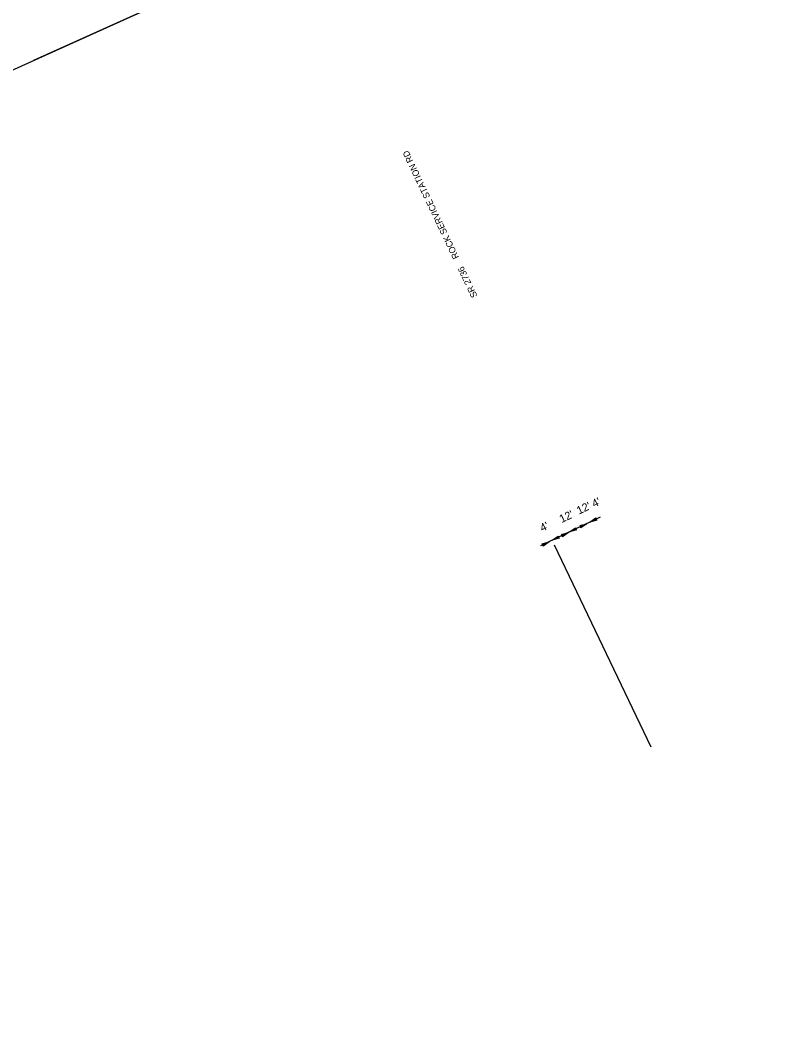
# Model space of a CAD drawing. Extents: x 2097307 to 2099001, y 683921 to 685907.
# Drawn here: x 2097686 to 2098154, y 684914 to 685550 of the extents above; entities that cross this region are included whole.
import ezdxf

# ---------------------------------------------------------------- set-up
doc = ezdxf.new("R2010")
doc.units = 0
for name, color, linetype in [('Default', 7, 'Continuous'), ('Matchline', 7, 'Continuous'), ('Prop Mkg Solid White Edge Line', 7, 'Continuous'), ('Sheet Layout Plan Border', 7, 'Continuous'), ('Text', 7, 'Continuous')]:
    doc.layers.add(name, color=color, linetype=linetype)

msp = doc.modelspace()

# ---------------------------------------------------------------- linework, layer by layer
at = {"layer": 'Default'}
msp.add_line((2098048.4, 685240), (2098011.01, 685222.07), dxfattribs=at)
for points in [[(2098035.72, 685234.78), (2098040.11, 685236.02), (2098036.38, 685233.35), (2098036.55, 685234.32)], [(2098046.38, 685238.17), (2098041.99, 685236.92), (2098045.72, 685239.6), (2098045.55, 685238.63)], [(2098022.8, 685226.87), (2098018.41, 685225.62), (2098022.14, 685228.3), (2098021.97, 685227.33)], [(2098024.19, 685229.25), (2098028.58, 685230.5), (2098024.85, 685227.82), (2098025.02, 685228.79)], [(2098033.69, 685232.08), (2098029.29, 685230.84), (2098033.03, 685233.51), (2098032.85, 685232.54)], [(2098012.14, 685223.48), (2098016.54, 685224.72), (2098012.8, 685222.04), (2098012.97, 685223.01)]]:
    msp.add_lwpolyline(points, close=True, dxfattribs=at)
at = {"layer": 'Matchline'}
msp.add_line((2097694.69, 685525.59), (2098013.7, 685669.59), dxfattribs=at)
at = {"layer": 'Prop Mkg Solid White Edge Line'}
msp.add_line((2098080.26, 685096.3), (2098019.77, 685222.59), dxfattribs=at)
at = {"layer": 'Sheet Layout Plan Border'}
msp.add_lwpolyline([(2098458.66, 685511.51), (2098911.14, 684517.12), (2097955.44, 684082.23), (2097420.98, 685256.77), (2097639.51, 685356.21), (2097584.97, 685476.06), (2098243.4, 685773.28), (2098379.01, 685475.27)], close=True, dxfattribs=at)

# ---------------------------------------------------------------- texts
at = {"layer": 'Text'}
for s, height, rotation, p in [('SR 2736    ROCK SERVICE STATION RD   ', 4, 115.42342, (2097971.8, 685378.34)), ("12'", 5, 25.61333, (2098035.13, 685241.63)), ("4'", 5, 25.61333, (2098044.64, 685245.94)), ("12'", 5, 25.61333, (2098024.34, 685236.37)), ("4'", 5, 25.61333, (2098012.22, 685230.83))]:
    msp.add_text(s, height=height, rotation=rotation, dxfattribs=at).set_placement(p)

doc.saveas('drawing.dxf')
